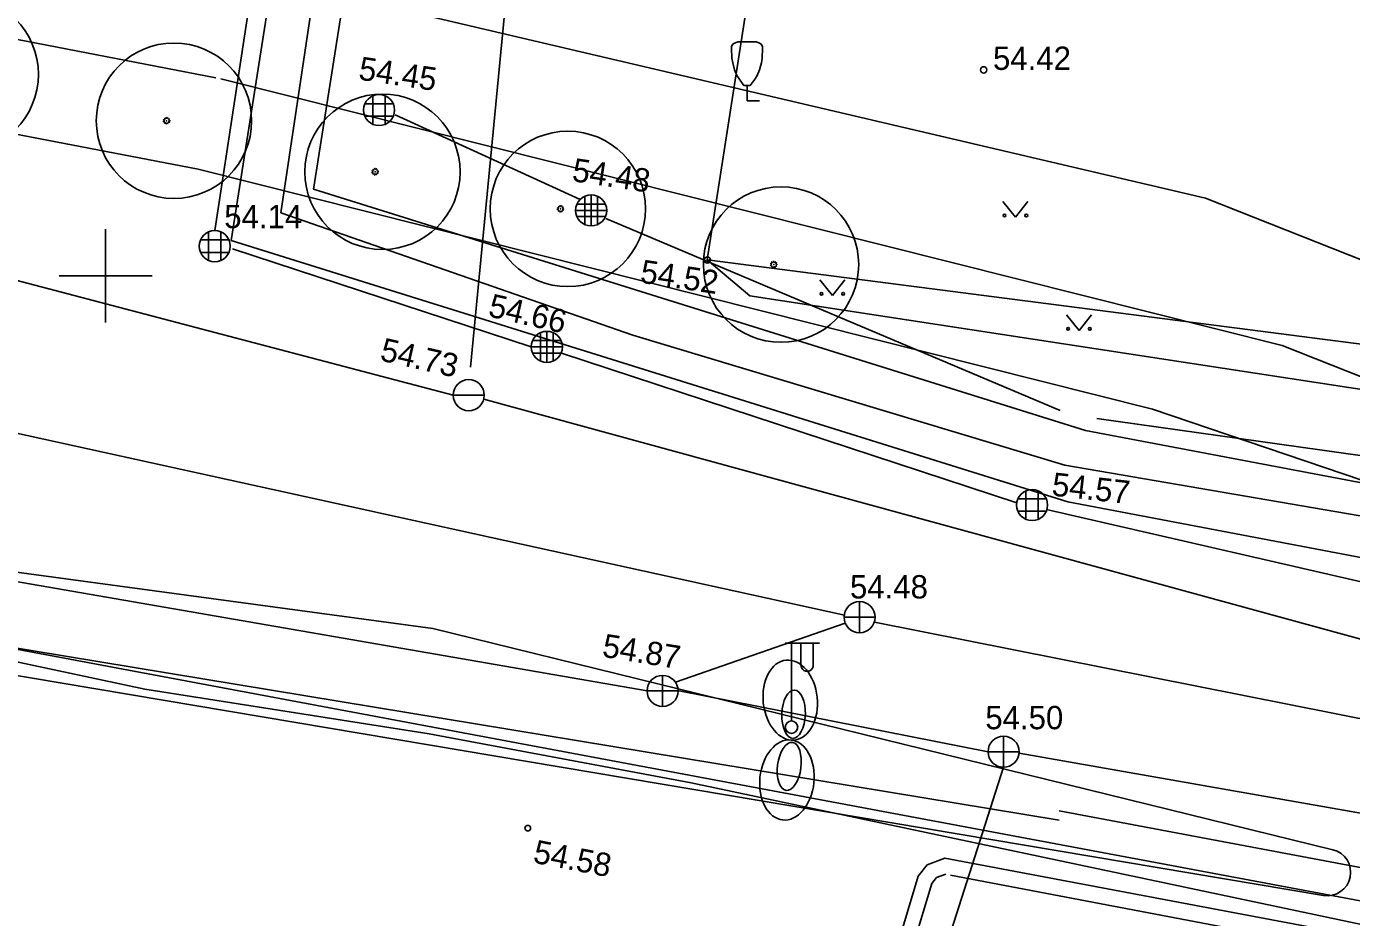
# Model space of a CAD drawing. Extents: x 9156 to 9809, y 2728 to 4000.
# Drawn here: x 9647.45 to 9690.1, y 3679.35 to 3708.02 of the extents above; entities that cross this region are included whole.
import ezdxf

# ---------------------------------------------------------------- set-up
doc = ezdxf.new("R2010")
doc.units = 0
for name, color, linetype in [('Level 16', 7, 'Continuous'), ('Level 17', 7, 'Continuous'), ('Level 18', 7, 'Continuous'), ('Level 54', 7, 'Continuous'), ('Level 56', 7, 'Continuous'), ('Level 8', 7, 'Continuous'), ('Level 9', 7, 'Continuous')]:
    doc.layers.add(name, color=color, linetype=linetype)

msp = doc.modelspace()

# ---------------------------------------------------------------- linework, layer by layer
at = {"layer": 'Level 16'}
for p, q in [((9613.76, 3693.514), (9680.691, 3682.486)), ((9680.691, 3682.788), (9760.055, 3667.827))]:
    msp.add_line(p, q, dxfattribs=at)
at = {"layer": 'Level 17'}
for p, q in [((9653.543, 3706.371), (9594.283, 3717.825)), ((9685.405, 3702.503), (9713.644, 3691.304)), ((9687.87, 3697.76), (9708.677, 3689.509)), ((9719.248, 3674.474), (9628.975, 3691.391))]:
    msp.add_line(p, q, dxfattribs=at)
for points in [[(9685.405, 3702.503), (9654.208, 3709.808)], [(9687.87, 3697.76), (9653.704, 3706.336)]]:
    msp.add_lwpolyline(points, dxfattribs=at)
at = {"layer": 'Level 18'}
for p, q in [((9652.974, 3703.426), (9593.714, 3714.88)), ((9689.202, 3680.064), (9529.882, 3706.858)), ((9660.53, 3688.652), (9610.092, 3695.469)), ((9683.7, 3695.714), (9711.256, 3686.333)), ((9660.53, 3688.652), (9689.506, 3681.532))]:
    msp.add_line(p, q, dxfattribs=at)
msp.add_lwpolyline([(9683.7, 3695.714), (9652.974, 3703.426)], dxfattribs=at)
msp.add_arc((9689.327, 3680.804), 0.75, 260.4536, 76.1947, dxfattribs=at)
at = {"layer": 'Level 54'}
for p, q in [((9661.749, 3697.064), (9664.999, 3730.984)), ((9669.366, 3700.509), (9673.228, 3725.271)), ((9669.366, 3700.509), (9673.228, 3725.271)), ((9655.635, 3702.029), (9658.912, 3723.787)), ((9653.51, 3701.454), (9656.525, 3721.132)), ((9670.346, 3707.525), (9670.946, 3707.525)), ((9670.346, 3707.525), (9670.946, 3707.525)), ((9670.546, 3706.125), (9670.746, 3706.125)), ((9670.546, 3706.125), (9670.746, 3706.125)), ((9670.646, 3705.625), (9670.646, 3706.125)), ((9670.646, 3705.625), (9670.646, 3706.125)), ((9658.6, 3705.793), (9658.6, 3704.876)), ((9659, 3705.793), (9659, 3704.876)), ((9670.646, 3705.625), (9671.046, 3705.625)), ((9670.646, 3705.625), (9671.046, 3705.625)), ((9658.341, 3705.534), (9659.258, 3705.534)), ((9665.274, 3702.457), (9659.316, 3705.182)), ((9658.341, 3705.134), (9659.258, 3705.134)), ((9661.189, 3696.158), (9634.565, 3703.164)), ((9665.17, 3702.303), (9666.086, 3702.303)), ((9665.428, 3702.561), (9665.428, 3701.645)), ((9665.628, 3702.103), (9665.628, 3702.603)), ((9665.628, 3702.103), (9665.628, 3702.603)), ((9665.828, 3702.561), (9665.828, 3701.645)), ((9678.885, 3702.39), (9679.286, 3701.886)), ((9679.286, 3701.886), (9679.685, 3702.39)), ((9666.974, 3698.085), (9655.635, 3702.029)), ((9665.628, 3702.103), (9665.128, 3702.103)), ((9665.628, 3702.103), (9665.128, 3702.103)), ((9665.17, 3701.903), (9666.086, 3701.903)), ((9665.628, 3702.103), (9666.128, 3702.103)), ((9665.628, 3702.103), (9665.628, 3701.603)), ((9665.628, 3702.103), (9666.128, 3702.103)), ((9665.628, 3702.103), (9665.628, 3701.603)), ((9680.724, 3695.667), (9666.105, 3701.843)), ((9650, 3701.5), (9650, 3698.5)), ((9653.31, 3701.412), (9653.31, 3700.496)), ((9653.71, 3701.412), (9653.71, 3700.496)), ((9653.052, 3701.154), (9653.968, 3701.154)), ((9653.052, 3700.754), (9653.968, 3700.754)), ((9663.701, 3697.713), (9654.081, 3700.872)), ((9648.5, 3700), (9651.5, 3700)), ((9672.99, 3699.869), (9673.393, 3699.364)), ((9673.393, 3699.364), (9673.79, 3699.869)), ((9680.93, 3698.745), (9681.333, 3698.239)), ((9681.333, 3698.239), (9681.73, 3698.745)), ((9664.001, 3698.171), (9664.001, 3697.255)), ((9664.201, 3697.713), (9664.201, 3698.213)), ((9664.201, 3697.713), (9664.201, 3698.213)), ((9664.401, 3698.171), (9664.401, 3697.255)), ((9680.878, 3693.909), (9666.974, 3698.085)), ((9664.201, 3697.713), (9663.701, 3697.713)), ((9664.201, 3697.713), (9663.701, 3697.713)), ((9663.743, 3697.913), (9664.659, 3697.913)), ((9663.743, 3697.513), (9664.659, 3697.513)), ((9664.201, 3697.713), (9664.701, 3697.713)), ((9664.201, 3697.713), (9664.201, 3697.213)), ((9664.201, 3697.713), (9664.701, 3697.713)), ((9664.201, 3697.713), (9664.201, 3697.213)), ((9664.669, 3697.515), (9679.328, 3692.695)), ((9673.785, 3689.085), (9643.225, 3695.796)), ((9661.189, 3696.158), (9662.189, 3696.158)), ((9661.189, 3696.158), (9662.189, 3696.158)), ((9691.692, 3687.955), (9662.174, 3696.032)), ((9693.542, 3693.769), (9681.903, 3695.413)), ((9694.178, 3691.621), (9680.878, 3693.909)), ((9679.365, 3692.824), (9680.281, 3692.824)), ((9679.623, 3693.082), (9679.623, 3692.166)), ((9680.023, 3693.082), (9680.023, 3692.166)), ((9679.365, 3692.424), (9680.281, 3692.424)), ((9680.291, 3692.482), (9691.152, 3689.985)), ((9719.248, 3674.474), (9628.975, 3691.391)), ((9667.427, 3686.641), (9644.103, 3690.687)), ((9674.269, 3689.015), (9674.269, 3689.515)), ((9674.269, 3689.015), (9673.769, 3689.015)), ((9674.269, 3689.015), (9674.769, 3689.015)), ((9674.269, 3689.015), (9674.269, 3688.515)), ((9668.339, 3686.924), (9673.809, 3688.818)), ((9674.744, 3688.858), (9727.149, 3678.46)), ((9671.879, 3688.177), (9672.979, 3688.177)), ((9672.079, 3688.177), (9672.079, 3685.677)), ((9672.379, 3688.177), (9672.379, 3687.477)), ((9672.779, 3688.177), (9672.779, 3687.477)), ((9667.927, 3686.641), (9667.927, 3687.141)), ((9667.927, 3686.641), (9667.427, 3686.641)), ((9667.927, 3686.641), (9668.427, 3686.641)), ((9667.927, 3686.641), (9667.927, 3686.141)), ((9678.404, 3684.688), (9668.458, 3686.641)), ((9678.904, 3684.688), (9678.904, 3685.188)), ((9678.904, 3684.688), (9678.404, 3684.688)), ((9678.904, 3684.688), (9679.404, 3684.688)), ((9678.904, 3684.688), (9678.904, 3684.188)), ((9708.328, 3679.577), (9679.401, 3684.636)), ((9673.558, 3667.474), (9678.904, 3684.188)), ((9676.446, 3681.049), (9676.152, 3680.681)), ((9677.017, 3681.264), (9676.446, 3681.049)), ((9716.5, 3673.808), (9677.017, 3681.264)), ((9676.152, 3680.681), (9673.031, 3670.299)), ((9676.593, 3680.449), (9673.5, 3670.159)), ((9676.744, 3680.638), (9676.593, 3680.449)), ((9677.046, 3680.752), (9676.744, 3680.638)), ((9715.597, 3673.433), (9677.197, 3680.714))]:
    msp.add_line(p, q, dxfattribs=at)
for points in [[(9695.017, 3692.471), (9681.545, 3695.027), (9656.694, 3702.787), (9660.162, 3724.853), (9656.065, 3725.674)], [(9694.576, 3690.145), (9680.969, 3692.726), (9654.037, 3701.136), (9657.47, 3722.977), (9655.6, 3723.353)], [(9694.576, 3690.145), (9680.969, 3692.726), (9654.037, 3701.136), (9657.47, 3722.977), (9655.6, 3723.353)], [(9669.366, 3700.509), (9706.561, 3695.721), (9760.177, 3687.877), (9760.263, 3708.241), (9757.403, 3709.459), (9722.811, 3716.105)], [(9670.546, 3706.125), (9670.388, 3706.338), (9670.323, 3706.45), (9670.246, 3706.625), (9670.185, 3706.85), (9670.161, 3707.006), (9670.146, 3707.325), (9670.148, 3707.367), (9670.178, 3707.438), (9670.218, 3707.475), (9670.346, 3707.525)], [(9670.546, 3706.125), (9670.388, 3706.338), (9670.323, 3706.45), (9670.246, 3706.625), (9670.185, 3706.85), (9670.161, 3707.006), (9670.146, 3707.325), (9670.148, 3707.367), (9670.178, 3707.438), (9670.218, 3707.475), (9670.346, 3707.525)], [(9670.746, 3706.125), (9670.904, 3706.338), (9670.969, 3706.45), (9671.046, 3706.625), (9671.107, 3706.85), (9671.131, 3707.006), (9671.146, 3707.325), (9671.144, 3707.367), (9671.114, 3707.438), (9671.074, 3707.475), (9670.946, 3707.525)], [(9670.746, 3706.125), (9670.904, 3706.338), (9670.969, 3706.45), (9671.046, 3706.625), (9671.107, 3706.85), (9671.131, 3707.006), (9671.146, 3707.325), (9671.144, 3707.367), (9671.114, 3707.438), (9671.074, 3707.475), (9670.946, 3707.525)], [(9668.849, 3683.691), (9716.728, 3673.571), (9733.181, 3670.306), (9749.81, 3667.577), (9753.185, 3667.02), (9755.937, 3666.713), (9759.285, 3666.165), (9760.87, 3667.83), (9761.204, 3674.559), (9762.185, 3706.838)], [(9761.574, 3686.738), (9760.208, 3685.671), (9670.741, 3699.357), (9669.366, 3700.509)], [(9668.849, 3683.691), (9660.411, 3685.262), (9651.262, 3686.7), (9637.816, 3689.558), (9618.019, 3693.118), (9599.826, 3696.295), (9598.985, 3696.55)]]:
    msp.add_lwpolyline(points, dxfattribs=at)
for centre, radius in [((9678.264, 3706.625), 0.102), ((9658.8, 3705.334), 0.5), ((9665.628, 3702.103), 0.5), ((9665.628, 3702.103), 0.5), ((9665.628, 3702.103), 0.5), ((9678.935, 3701.94), 0.0433), ((9679.635, 3701.94), 0.0482), ((9653.51, 3700.954), 0.5), ((9669.366, 3700.509), 0.102), ((9673.04, 3699.419), 0.0428), ((9673.74, 3699.419), 0.0452), ((9664.201, 3697.713), 0.5), ((9664.201, 3697.713), 0.5), ((9664.201, 3697.713), 0.5), ((9680.98, 3698.295), 0.0428), ((9681.68, 3698.295), 0.0452), ((9661.689, 3696.158), 0.5), ((9661.689, 3696.158), 0.5), ((9679.823, 3692.624), 0.5), ((9674.269, 3689.015), 0.5), ((9667.927, 3686.641), 0.5), ((9672.079, 3685.477), 0.2), ((9678.904, 3684.688), 0.5), ((9663.587, 3682.227), 0.0909)]:
    msp.add_circle(centre, radius, dxfattribs=at)
msp.add_arc((9672.579, 3687.477), 0.2, 179.9393, 0.0607, dxfattribs=at)
at = {"layer": 'Level 56'}
for p, q in [((9653.543, 3706.371), (9594.283, 3717.825)), ((9652.974, 3703.426), (9593.714, 3714.88)), ((9689.202, 3680.064), (9529.882, 3706.858)), ((9685.405, 3702.503), (9713.644, 3691.304)), ((9687.87, 3697.76), (9708.677, 3689.509)), ((9660.53, 3688.652), (9610.092, 3695.469)), ((9683.7, 3695.714), (9711.256, 3686.333)), ((9660.53, 3688.652), (9689.506, 3681.532))]:
    msp.add_line(p, q, dxfattribs=at)
for points in [[(9685.405, 3702.503), (9654.208, 3709.808)], [(9687.87, 3697.76), (9653.704, 3706.336)], [(9683.7, 3695.714), (9652.974, 3703.426)]]:
    msp.add_lwpolyline(points, dxfattribs=at)
msp.add_arc((9689.327, 3680.804), 0.75, 260.4536, 76.1947, dxfattribs=at)
at = {"layer": 'Level 8'}
for centre, major_axis, ratio in [((9672.038, 3686.349), (0.134, -1.286), 0.674652), ((9672.038, 3686.349), (0.134, -1.286), 0.674652), ((9672.038, 3686.349), (0.134, -1.286), 0.674652), ((9672.038, 3686.349), (0.134, -1.286), 0.674652), ((9672.145, 3685.894), (-0.027, -0.777), 0.486914), ((9672.145, 3685.894), (-0.027, -0.777), 0.486914), ((9672.145, 3685.894), (-0.027, -0.777), 0.486914), ((9672.145, 3685.894), (-0.027, -0.777), 0.486914), ((9671.931, 3683.777), (0.134, 1.286), 0.674652), ((9671.931, 3683.777), (0.134, 1.286), 0.674652), ((9671.931, 3683.777), (0.134, 1.286), 0.674652), ((9671.931, 3683.777), (0.134, 1.286), 0.674652), ((9672.004, 3684.213), (0.102, 0.771), 0.486914), ((9672.004, 3684.213), (0.102, 0.771), 0.486914), ((9672.004, 3684.213), (0.102, 0.771), 0.486914), ((9672.004, 3684.213), (0.102, 0.771), 0.486914)]:
    msp.add_ellipse(centre, major_axis=major_axis, ratio=ratio, dxfattribs=at)
at = {"layer": 'Level 9'}
for p, q in [((9651.885, 3705.002), (9651.863, 3705.005)), ((9651.863, 3704.976), (9651.885, 3704.98)), ((9651.871, 3705.032), (9651.892, 3705.024)), ((9651.891, 3704.958), (9651.871, 3704.948)), ((9651.886, 3704.925), (9651.903, 3704.939)), ((9651.904, 3705.042), (9651.887, 3705.056)), ((9651.908, 3705.075), (9651.92, 3705.056)), ((9651.92, 3704.924), (9651.908, 3704.906)), ((9651.941, 3705.066), (9651.934, 3705.087)), ((9651.934, 3704.894), (9651.94, 3704.915)), ((9651.973, 3704.989), (9651.952, 3704.989)), ((9651.963, 3704.912), (9651.962, 3704.89)), ((9651.963, 3705.091), (9651.963, 3705.069)), ((9651.963, 3704.979), (9651.963, 3705)), ((9651.984, 3705.066), (9651.99, 3705.087)), ((9651.99, 3704.894), (9651.985, 3704.915)), ((9652.005, 3704.924), (9652.017, 3704.906)), ((9652.017, 3705.075), (9652.006, 3705.056)), ((9652.022, 3705.042), (9652.039, 3705.056)), ((9652.04, 3704.925), (9652.023, 3704.94)), ((9652.054, 3705.032), (9652.035, 3705.022)), ((9652.035, 3704.958), (9652.055, 3704.95)), ((9652.041, 3705.001), (9652.062, 3705.005)), ((9652.062, 3704.977), (9652.041, 3704.98)), ((9658.598, 3703.36), (9658.576, 3703.363)), ((9658.576, 3703.334), (9658.597, 3703.338)), ((9658.584, 3703.39), (9658.604, 3703.382)), ((9658.604, 3703.316), (9658.584, 3703.306)), ((9658.599, 3703.283), (9658.616, 3703.297)), ((9658.616, 3703.4), (9658.6, 3703.414)), ((9658.621, 3703.433), (9658.633, 3703.414)), ((9658.633, 3703.282), (9658.621, 3703.264)), ((9658.654, 3703.424), (9658.647, 3703.445)), ((9658.647, 3703.252), (9658.653, 3703.273)), ((9658.686, 3703.347), (9658.665, 3703.347)), ((9658.676, 3703.269), (9658.675, 3703.248)), ((9658.676, 3703.449), (9658.676, 3703.427)), ((9658.676, 3703.337), (9658.676, 3703.358)), ((9658.697, 3703.424), (9658.703, 3703.445)), ((9658.703, 3703.251), (9658.698, 3703.273)), ((9658.718, 3703.281), (9658.73, 3703.263)), ((9658.73, 3703.433), (9658.719, 3703.414)), ((9658.735, 3703.4), (9658.752, 3703.414)), ((9658.752, 3703.283), (9658.736, 3703.298)), ((9658.767, 3703.39), (9658.748, 3703.38)), ((9658.748, 3703.316), (9658.768, 3703.307)), ((9658.754, 3703.359), (9658.775, 3703.363)), ((9658.775, 3703.335), (9658.754, 3703.338)), ((9664.551, 3702.196), (9664.571, 3702.188)), ((9664.583, 3702.206), (9664.567, 3702.22)), ((9664.588, 3702.238), (9664.6, 3702.22)), ((9664.621, 3702.23), (9664.614, 3702.25)), ((9664.643, 3702.254), (9664.643, 3702.233)), ((9664.664, 3702.23), (9664.67, 3702.251)), ((9664.697, 3702.239), (9664.686, 3702.22)), ((9664.702, 3702.206), (9664.719, 3702.22)), ((9664.734, 3702.196), (9664.715, 3702.186)), ((9664.565, 3702.165), (9664.543, 3702.168)), ((9664.543, 3702.14), (9664.565, 3702.143)), ((9664.571, 3702.121), (9664.551, 3702.112)), ((9664.566, 3702.088), (9664.583, 3702.103)), ((9664.6, 3702.087), (9664.588, 3702.069)), ((9664.614, 3702.057), (9664.62, 3702.078)), ((9664.653, 3702.153), (9664.632, 3702.153)), ((9664.643, 3702.075), (9664.642, 3702.053)), ((9664.643, 3702.142), (9664.643, 3702.163)), ((9664.67, 3702.057), (9664.665, 3702.078)), ((9664.685, 3702.087), (9664.697, 3702.069)), ((9664.719, 3702.089), (9664.703, 3702.103)), ((9664.715, 3702.122), (9664.735, 3702.113)), ((9664.721, 3702.165), (9664.742, 3702.169)), ((9664.742, 3702.14), (9664.721, 3702.144)), ((9671.427, 3700.374), (9671.405, 3700.377)), ((9671.405, 3700.348), (9671.427, 3700.352)), ((9671.413, 3700.404), (9671.434, 3700.396)), ((9671.433, 3700.33), (9671.413, 3700.32)), ((9671.428, 3700.297), (9671.445, 3700.311)), ((9671.446, 3700.414), (9671.429, 3700.428)), ((9671.45, 3700.447), (9671.462, 3700.428)), ((9671.462, 3700.296), (9671.45, 3700.278)), ((9671.483, 3700.438), (9671.476, 3700.459)), ((9671.476, 3700.266), (9671.482, 3700.287)), ((9671.515, 3700.361), (9671.494, 3700.361)), ((9671.505, 3700.284), (9671.504, 3700.262)), ((9671.505, 3700.463), (9671.505, 3700.441)), ((9671.505, 3700.351), (9671.505, 3700.372)), ((9671.526, 3700.438), (9671.532, 3700.459)), ((9671.532, 3700.266), (9671.527, 3700.287)), ((9671.547, 3700.296), (9671.559, 3700.278)), ((9671.559, 3700.447), (9671.548, 3700.428)), ((9671.564, 3700.414), (9671.581, 3700.428)), ((9671.582, 3700.297), (9671.565, 3700.312)), ((9671.596, 3700.404), (9671.577, 3700.394)), ((9671.577, 3700.33), (9671.597, 3700.322)), ((9671.583, 3700.373), (9671.604, 3700.377)), ((9671.604, 3700.349), (9671.583, 3700.352))]:
    msp.add_line(p, q, dxfattribs=at)
for centre in [(9645.336, 3706.482), (9652.198, 3704.989), (9658.911, 3703.347), (9664.878, 3702.153), (9671.74, 3700.361)]:
    msp.add_circle(centre, 2.5, dxfattribs=at)
for centre, radius, start, end in [((9651.963, 3704.99), 0.101, 155.3123, 171.7042), ((9651.963, 3704.99), 0.101, 187.9671, 204.8625), ((9651.963, 3704.99), 0.0788, 171.5431, 187.6203), ((9651.963, 3704.99), 0.101, 220.7122, 237.1166), ((9651.963, 3704.99), 0.101, 122.8434, 139.0222), ((9651.963, 3704.99), 0.0788, 204.4529, 220.4774), ((9651.963, 3704.99), 0.0788, 138.6432, 154.5795), ((9651.963, 3704.99), 0.0788, 105.9559, 123.0564), ((9651.963, 3704.99), 0.0788, 237.451, 253.0843), ((9651.963, 3704.99), 0.101, 90.0356, 106.342), ((9651.963, 3704.99), 0.101, 253.2952, 269.5718), ((9651.963, 3704.99), 0.0788, 74.31, 90.043), ((9651.963, 3704.99), 0.0788, 269.9461, 286.3473), ((9651.963, 3704.99), 0.101, 57.6108, 74.1981), ((9651.963, 3704.99), 0.101, 285.972, 302.5562), ((9651.963, 3704.99), 0.0788, 302.254, 320.086), ((9651.963, 3704.99), 0.0788, 41.2062, 56.7795), ((9651.963, 3704.99), 0.0788, 8.0619, 24.0332), ((9651.963, 3704.99), 0.0788, 336.0557, 352.7558), ((9651.963, 3704.99), 0.101, 24.5394, 40.9852), ((9651.963, 3704.99), 0.101, 319.7777, 336.0738), ((9651.963, 3704.99), 0.101, 352.27, 8.583), ((9658.676, 3703.348), 0.101, 155.3123, 171.7042), ((9658.676, 3703.348), 0.101, 187.9671, 204.8625), ((9658.676, 3703.348), 0.0788, 171.5431, 187.6203), ((9658.676, 3703.348), 0.101, 220.7122, 237.1166), ((9658.676, 3703.348), 0.101, 122.8434, 139.0222), ((9658.676, 3703.348), 0.0788, 138.6432, 154.5795), ((9658.676, 3703.348), 0.0788, 204.4529, 220.4774), ((9658.676, 3703.348), 0.0788, 105.9559, 123.0564), ((9658.676, 3703.348), 0.0788, 237.451, 253.0843), ((9658.676, 3703.348), 0.101, 90.0356, 106.342), ((9658.676, 3703.348), 0.101, 253.2952, 269.5718), ((9658.676, 3703.348), 0.0788, 74.31, 90.043), ((9658.676, 3703.348), 0.0788, 269.9461, 286.3473), ((9658.676, 3703.348), 0.101, 57.6108, 74.1981), ((9658.676, 3703.348), 0.101, 285.972, 302.5562), ((9658.676, 3703.348), 0.0788, 302.254, 320.086), ((9658.676, 3703.348), 0.0788, 41.2062, 56.7795), ((9658.676, 3703.348), 0.0788, 8.0619, 24.0332), ((9658.676, 3703.348), 0.0788, 336.0557, 352.7558), ((9658.676, 3703.348), 0.101, 24.5394, 40.9852), ((9658.676, 3703.348), 0.101, 319.7777, 336.0738), ((9658.676, 3703.348), 0.101, 352.27, 8.583), ((9664.643, 3702.154), 0.101, 155.3123, 171.7042), ((9664.643, 3702.154), 0.101, 122.8434, 139.0222), ((9664.643, 3702.154), 0.0788, 138.6432, 154.5795), ((9664.643, 3702.154), 0.0788, 105.9559, 123.0564), ((9664.643, 3702.154), 0.101, 90.0356, 106.342), ((9664.643, 3702.154), 0.0788, 74.31, 90.043), ((9664.643, 3702.154), 0.101, 57.6108, 74.1981), ((9664.643, 3702.154), 0.0788, 41.2062, 56.7795), ((9664.643, 3702.154), 0.101, 24.5394, 40.9852), ((9664.643, 3702.154), 0.101, 187.9671, 204.8625), ((9664.643, 3702.154), 0.0788, 171.5431, 187.6203), ((9664.643, 3702.154), 0.101, 220.7122, 237.1166), ((9664.643, 3702.154), 0.0788, 204.4529, 220.4774), ((9664.643, 3702.154), 0.0788, 237.451, 253.0843), ((9664.643, 3702.154), 0.101, 253.2952, 269.5718), ((9664.643, 3702.154), 0.0788, 269.9461, 286.3473), ((9664.643, 3702.154), 0.101, 285.972, 302.5562), ((9664.643, 3702.154), 0.0788, 302.254, 320.086), ((9664.643, 3702.154), 0.0788, 8.0619, 24.0332), ((9664.643, 3702.154), 0.0788, 336.0557, 352.7558), ((9664.643, 3702.154), 0.101, 319.7777, 336.0738), ((9664.643, 3702.154), 0.101, 352.27, 8.583), ((9671.505, 3700.362), 0.101, 155.3123, 171.7042), ((9671.505, 3700.362), 0.101, 187.9671, 204.8625), ((9671.505, 3700.362), 0.0788, 171.5431, 187.6203), ((9671.505, 3700.362), 0.101, 220.7122, 237.1166), ((9671.505, 3700.362), 0.101, 122.8434, 139.0222), ((9671.505, 3700.362), 0.0788, 204.4529, 220.4774), ((9671.505, 3700.362), 0.0788, 138.6432, 154.5795), ((9671.505, 3700.362), 0.0788, 105.9559, 123.0564), ((9671.505, 3700.362), 0.0788, 237.451, 253.0843), ((9671.505, 3700.362), 0.101, 90.0356, 106.342), ((9671.505, 3700.362), 0.101, 253.2952, 269.5718), ((9671.505, 3700.362), 0.0788, 74.31, 90.043), ((9671.505, 3700.362), 0.0788, 269.9461, 286.3473), ((9671.505, 3700.362), 0.101, 57.6108, 74.1981), ((9671.505, 3700.362), 0.101, 285.972, 302.5562), ((9671.505, 3700.362), 0.0788, 302.254, 320.086), ((9671.505, 3700.362), 0.0788, 41.2062, 56.7795), ((9671.505, 3700.362), 0.0788, 8.0619, 24.0332), ((9671.505, 3700.362), 0.0788, 336.0557, 352.7558), ((9671.505, 3700.362), 0.101, 24.5394, 40.9852), ((9671.505, 3700.362), 0.101, 319.7777, 336.0738), ((9671.505, 3700.362), 0.101, 352.27, 8.583)]:
    msp.add_arc(centre, radius, start, end, dxfattribs=at)

# ---------------------------------------------------------------- texts
at = {"layer": 'Level 54'}
for s, p in [('54.42', (9678.564, 3706.625)), ('54.14', (9653.817, 3701.532)), ('54.48', (9673.96, 3689.618)), ('54.50', (9678.316, 3685.41))]:
    msp.add_text(s, height=0.75, dxfattribs=at).set_placement(p)
for s, rotation, p in [('54.45', 351.4486, (9658.114, 3706.317)), ('54.48', 351.4486, (9664.987, 3703.05)), ('54.52', 351.4486, (9667.18, 3699.783)), ('54.66', 347.1163, (9662.283, 3698.701)), ('54.73', 347.1163, (9658.8, 3697.282)), ('54.57', 353.6439, (9680.434, 3692.931)), ('54.87', 350.701, (9665.956, 3687.748)), ('54.58', 349.1007, (9663.731, 3681.122))]:
    msp.add_text(s, height=0.75, rotation=rotation, dxfattribs=at).set_placement(p)

doc.saveas('drawing.dxf')
